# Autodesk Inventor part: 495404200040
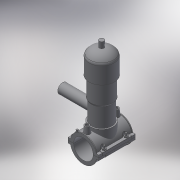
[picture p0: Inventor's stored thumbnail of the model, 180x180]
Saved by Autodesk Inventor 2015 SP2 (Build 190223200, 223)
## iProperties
Created: 2017-07
Part Number: 495404200040
Material: Generic
Description: PLASSON TAPPING VALVE 200-40
Document SubType Name: Modeling
Designer: KIM
Density: 1 g/cm^3
Appearance: Default
Author: KIM
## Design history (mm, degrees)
derived "495404-4954S4.ipt"
feature "Solid1::495404-4954S4.ipt"
feature "Solid2::495404-4954S4.ipt"
tag "TaggingFeature1"
body "Solid1"
body "Solid2"
other parameters: "d2" = 262.6, "d4" = 176, "d5" = 0, "d6" = 0.1, "d8" = 0, "d19" = 6, "d20" = 6, "d21" = 105.6, "d23" = 0, "d24" = 52.8, "d26" = 0, "d27" = 3, "d28" = 3, "d29" = 3, "d30" = 66.66667, "d31" = 6, "d32" = 0, "d33" = 0, "d34" = 0.6, "d40" = 121.68, "d47" = 163, "d70" = 15, "d72" = 0, "d73" = 6, "d75" = 5, "d76" = 0, "d79" = 15, "d80" = 70.4, "d82" = 5 deg, "d84" = 4, "d85" = 14, "d86" = 0, "d87" = 3, "d88" = 0, "d89" = 1, "d90" = 1, "d91" = 140.8, "d92" = 0, "d93" = 0.5, "d94" = 105.26316, "d96" = 241.02, "d97" = 3.52, "d98" = 0, "d120" = 140 deg, "d121" = 24.228, "d122" = 20 deg, "d123" = 468, "d124" = 140.4, "d126" = 0, "d143" = 206, "d145" = 26.15385, "d149" = 3, "d150" = 28.76923, "d153" = 176, "d154" = 0, "d156" = 117, "d157" = 160 deg, "d159" = 6.8, "d161" = 3, "d162" = 105.6, "d163" = 0, "d168" = 114.14634, "d170" = 3, "d172" = 0, "d173" = 1, "d176" = 20 deg, "d177" = 14, "d178" = 34, "d180" = 0, "d183" = 13.6, "d184" = 11.2, "d185" = 57.2, "d186" = 57.2, "d187" = 117, "d188" = 10.2, "d189" = 14, "d190" = 0, "d191" = 175.5, "d193" = 6.8, "d194" = 4.4, "d195" = 90 deg, "d197" = 0, "d199" = 0, "d205" = 14.64, "d206" = 81.33333, "d207" = 244, "d208" = 224.48, "d209" = 207.4, "d210" = 200.08, "d211" = 146.4, "d212" = 85.4, "d213" = 65.88, "d214" = 73.2, "d216" = 21.96, "d217" = 70.76, "d218" = 80.52, "d222" = 0, "d223" = 234, "d224" = 137, "d225" = 46, "d229" = 137, "d230" = 0, "B_" = 202, "H_" = 137, "L_" = 176, "d_t" = 6, "H_1" = 46, "H_2" = 244, "d148" = 3, "d160" = 3, "d169" = 3, "d192" = 6.8, "d228" = 32
